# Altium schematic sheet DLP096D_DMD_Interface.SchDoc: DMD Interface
size 431 x 279 mm; Date: Not shown in title block; ApprovedBy: Not shown in title block; CheckedBy: Not shown in title block; Author: Not shown in title block; CompanyName: Not shown in title block; Engineer: Not shown in title block; Organization: Not shown in title block; Address1: Not shown in title block; Address2: Not shown in title block; Address3: Not shown in title block; Address4: Not shown in title block; DocumentNumber: 6; Revision: Use project parameter SCH_Rev; SheetNumber: 6; SheetTotal: 10; PageSetup: Record=PageOptions¦CenterHorizontal=True¦CenterVertical=True¦PrintScale=1.00¦XCorrection=1.00¦YCorrection=1.00¦PrintKind=0¦BorderSize=5000000¦LeftOffset=0¦BottomOffset=0¦Orientation=2¦PaperLength=1000¦PaperWidth=1000¦Scale=100¦PaperSource=15¦PrintQuality=600¦MediaType=1¦DitherType=10¦PaperKind=Letter¦PrintScaleMode=1
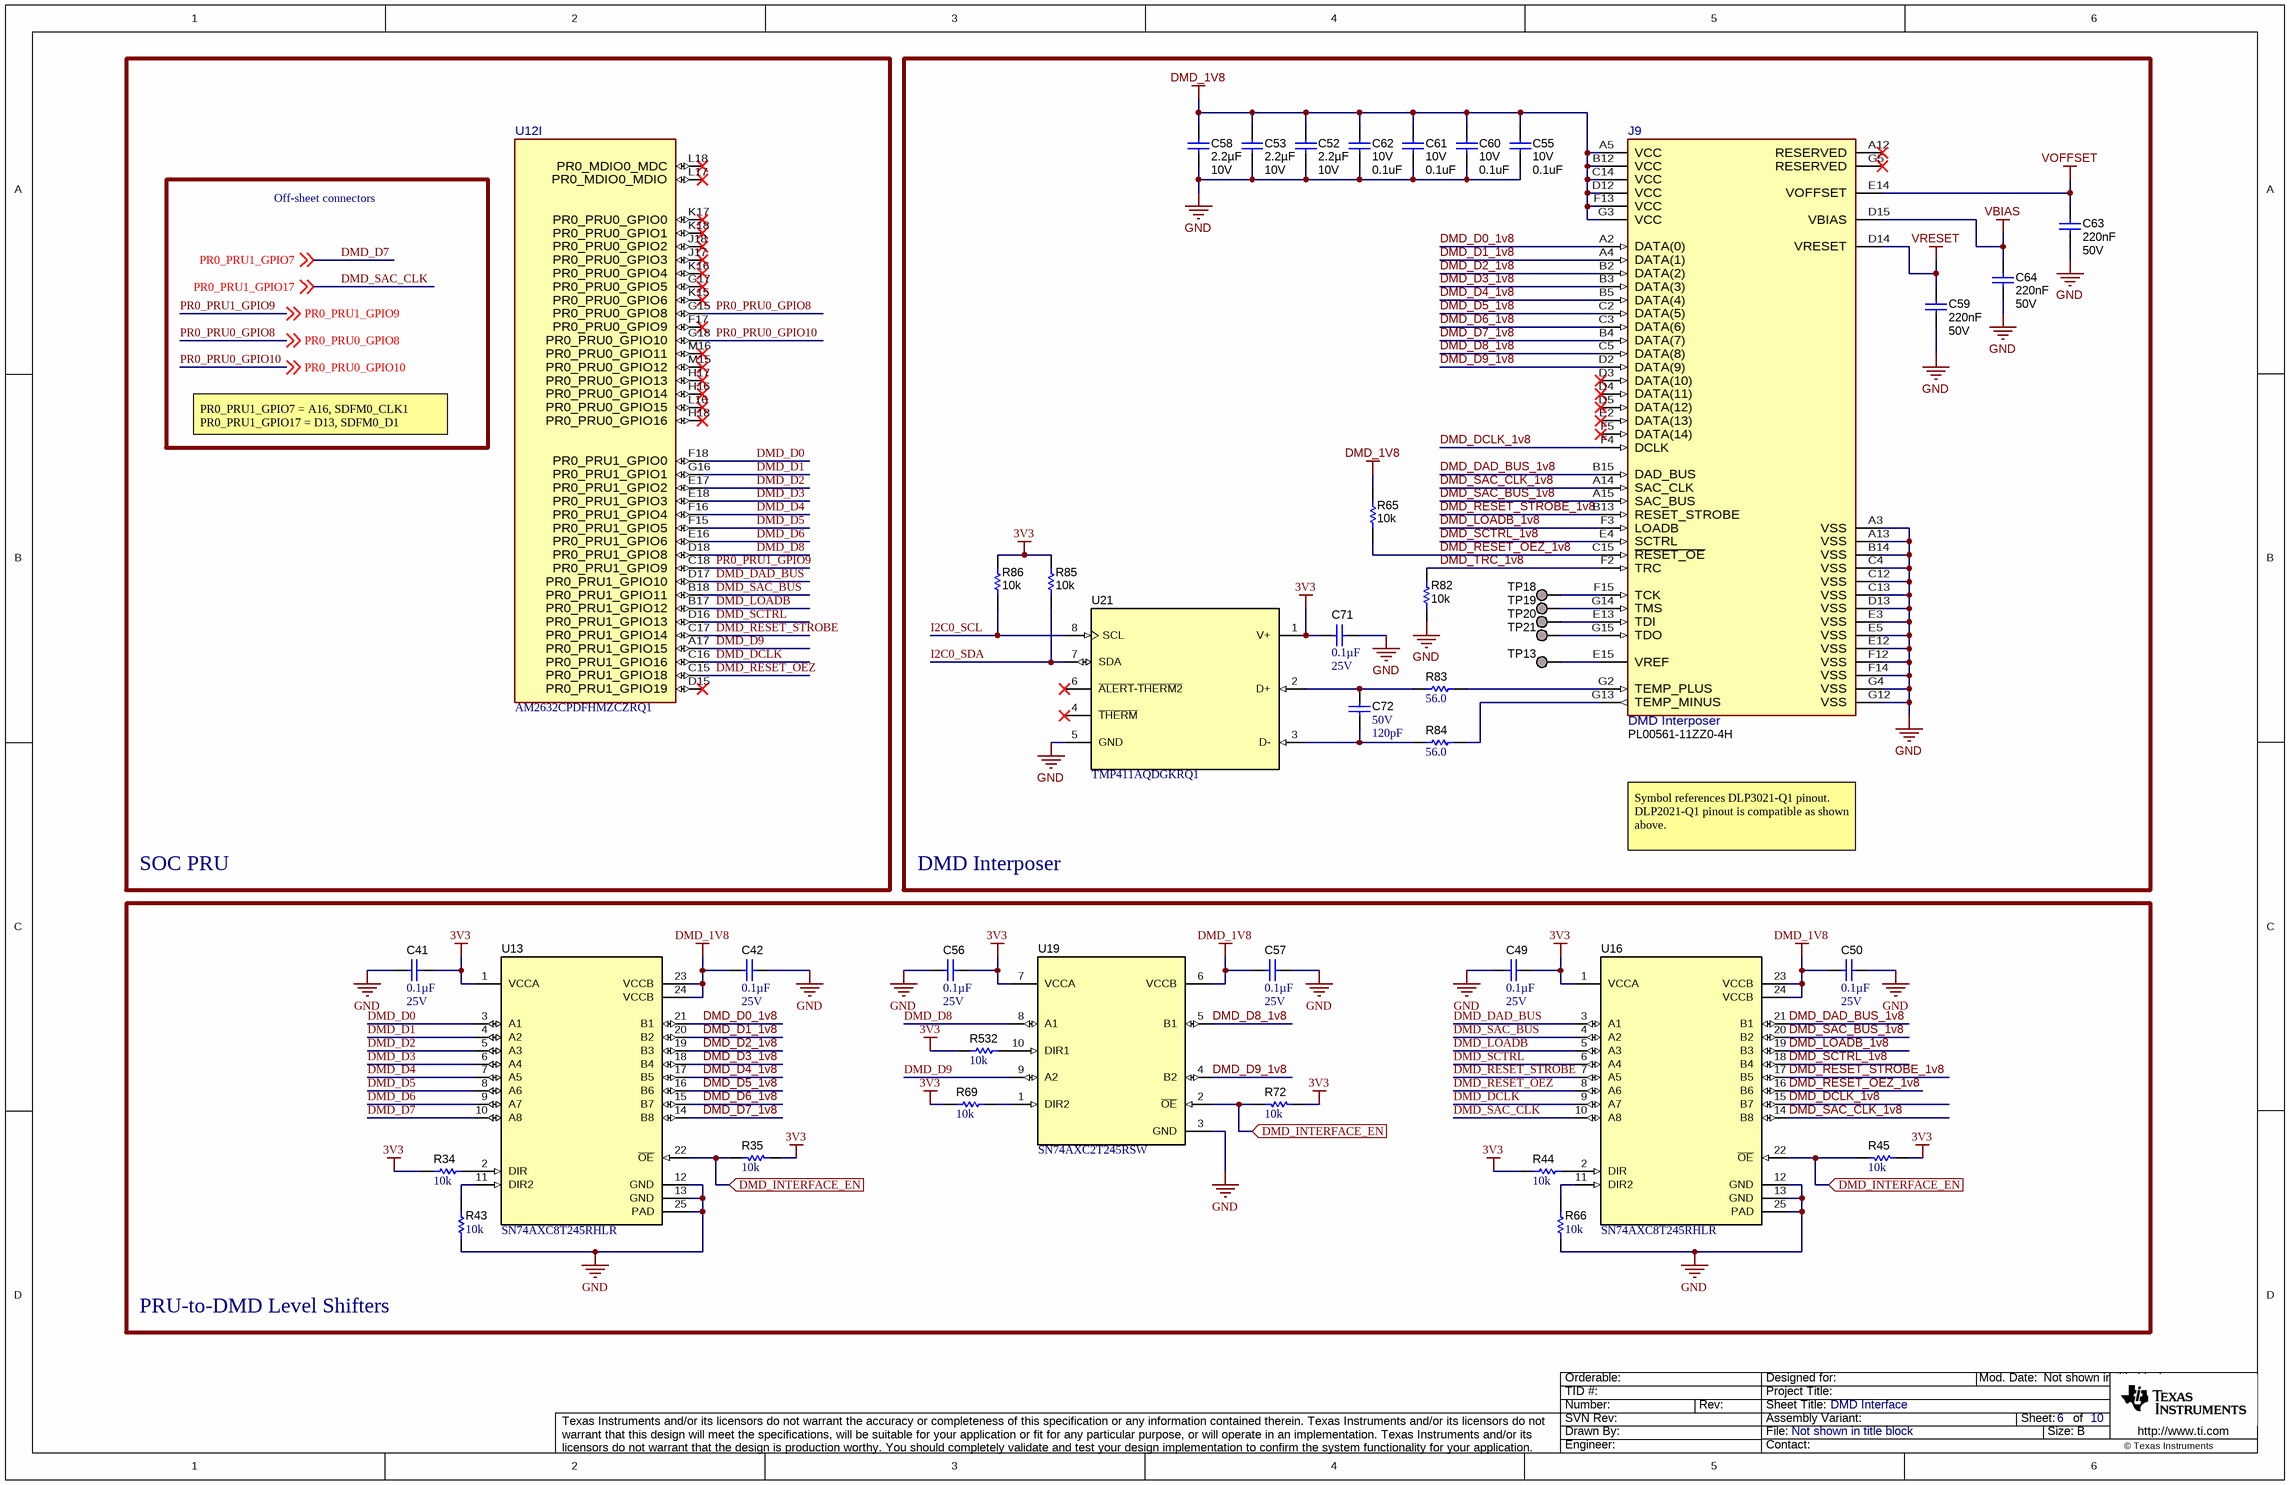
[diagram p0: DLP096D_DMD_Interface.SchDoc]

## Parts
C41  ValueDisplayed: 0.1µF  VDC_V: 25V  [0402]  (hidden comment: GCM155L81E104KE02D)
C42  ValueDisplayed: 0.1µF  VDC_V: 25V  [0402]  (hidden comment: GCM155L81E104KE02D)
C49  ValueDisplayed: 0.1µF  VDC_V: 25V  [0402]  (hidden comment: GCM155L81E104KE02D)
C50  ValueDisplayed: 0.1µF  VDC_V: 25V  [0402]  (hidden comment: GCM155L81E104KE02D)
C52  Cap_F: 2.2µF  VDC_V: 10V  [0603L]  (hidden comment: GRM188R71A225KE15J)
C53  Cap_F: 2.2µF  VDC_V: 10V  [0603L]  (hidden comment: GRM188R71A225KE15J)
C55  VDC_V: 10V  ValueDisplayed: 0.1uF  [0402L]  (hidden comment: GCM155R71A104KA55D)
C56  ValueDisplayed: 0.1µF  VDC_V: 25V  [0402]  (hidden comment: GCM155L81E104KE02D)
C57  ValueDisplayed: 0.1µF  VDC_V: 25V  [0402]  (hidden comment: GCM155L81E104KE02D)
C58  Cap_F: 2.2µF  VDC_V: 10V  [0603L]  (hidden comment: GRM188R71A225KE15J)
C59  Cap_F: 220nF  VDC_V: 50V  [0603L]  (hidden comment: GCM188R71E104KA57D)
C60  VDC_V: 10V  ValueDisplayed: 0.1uF  [0402L]  (hidden comment: GCM155R71A104KA55D)
C61  VDC_V: 10V  ValueDisplayed: 0.1uF  [0402L]  (hidden comment: GCM155R71A104KA55D)
C62  VDC_V: 10V  ValueDisplayed: 0.1uF  [0402L]  (hidden comment: GCM155R71A104KA55D)
C63  Cap_F: 220nF  VDC_V: 50V  [0603L]  (hidden comment: GCM188R71E104KA57D)
C64  Cap_F: 220nF  VDC_V: 50V  [0603L]  (hidden comment: GCM188R71E104KA57D)
C71  ValueDisplayed: 0.1µF  VDC_V: 25V  [0402]  (hidden comment: GCM155L81E104KE02D)
C72  VDC_V: 50V  ValueDisplayed: 120pF  [0402]  (hidden comment: GRM1555C1H121FA01D)
J9  DMD Interposer  PartNumber: PL00561-11ZZ0-4H  [FP-2516672_SMD_CONN_LGA-56-MFG]
R34  ValueDisplayed: 10k  [0603]  (hidden comment: CRCW060310K0JNEA)
R35  ValueDisplayed: 10k  [0603]  (hidden comment: CRCW060310K0JNEA)
R43  ValueDisplayed: 10k  [0603]  (hidden comment: CRCW060310K0JNEA)
R44  ValueDisplayed: 10k  [0603]  (hidden comment: CRCW060310K0JNEA)
R45  ValueDisplayed: 10k  [0603]  (hidden comment: CRCW060310K0JNEA)
R65  ValueDisplayed: 10k  [0201]  (hidden comment: RC0201JR-0710KL)
R66  ValueDisplayed: 10k  [0603]  (hidden comment: CRCW060310K0JNEA)
R69  ValueDisplayed: 10k  [0603]  (hidden comment: CRCW060310K0JNEA)
R72  ValueDisplayed: 10k  [0603]  (hidden comment: CRCW060310K0JNEA)
R82  ValueDisplayed: 10k  [0201]  (hidden comment: RC0201JR-0710KL)
R83  ValueDisplayed: 56.0  [0603]  (hidden comment: RC0603FR-0756RL)
R84  ValueDisplayed: 56.0  [0603]  (hidden comment: RC0603FR-0756RL)
R85  ValueDisplayed: 10k  [0201]  (hidden comment: RC0201JR-0710KL)
R86  ValueDisplayed: 10k  [0201]  (hidden comment: RC0201JR-0710KL)
R532  ValueDisplayed: 10k  [0603]  (hidden comment: CRCW060310K0JNEA)
TP13  TP_H0.45P0.75  [TP_H045P075]  (value not drawn)  (no BOM)
TP18  TP_H0.45P0.75  [TP_H045P075]  (value not drawn)  (no BOM)
TP19  TP_H0.45P0.75  [TP_H045P075]  (value not drawn)  (no BOM)
TP20  TP_H0.45P0.75  [TP_H045P075]  (value not drawn)  (no BOM)
TP21  TP_H0.45P0.75  [TP_H045P075]  (value not drawn)  (no BOM)
U12  AM2632CPDFHMZCZRQ1  [ZCZ0324A-MFG]  (part I of 13)
U13  SN74AXC8T245RHLR  [RHL0024A]
U16  SN74AXC8T245RHLR  [RHL0024A]
U19  SN74AXC2T245RSW  [RSW0010A]
U21  TMP411AQDGKRQ1  [DGK0008A_N]

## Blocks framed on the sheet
SOC PRU: U12
DMD Interposer: C52 C53 C55 C58-C64 C71 C72 J9 R65 R82-R86 TP13 TP18-TP21 U21
PRU-to-DMD Level Shifters: C41 C42 C49 C50 C56 C57 R34 R35 R43-R45 R66 R69 R72 R532 U13 U16 U19

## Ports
DMD_INTERFACE_EN (in)

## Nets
3V3: C41.1 C49.1 C56.1 C71.1 R34.1 R35.1 R44.1 R45.1 R69.2 R72.1 R85.2 R86.2 R532.1 U13.1(VCCA) U16.1(VCCA) U19.7(VCCA) U21.1(V+)
DMD_1V8: C42.2 C50.2 C52.1 C53.1 C55.1 C57.2 C58.1 C60.1 C61.1 C62.1 J9.A5(VCC) J9.B12(VCC) J9.C14(VCC) J9.D12(VCC) J9.F13(VCC) J9.G3(VCC) R65.2 U13.23(VCCB) U13.24(VCCB) U16.23(VCCB) U16.24(VCCB) U19.6(VCCB)
GND: C41.2 C42.1 C49.2 C50.1 C52.2 C53.2 C55.2 C56.2 C57.1 C58.2 C59.2 C60.2 C61.2 C62.2 C63.2 C64.2 C71.2 J9.A3(VSS) J9.A13(VSS) J9.B14(VSS) J9.C4(VSS) J9.C12(VSS) J9.C13(VSS) J9.D13(VSS) J9.E3(VSS) J9.E5(VSS) J9.E12(VSS) J9.F12(VSS) J9.F14(VSS) J9.G4(VSS) J9.G12(VSS) R43.1 R66.1 R82.1 U13.12(GND) U13.13(GND) U13.25(PAD) U16.12(GND) U16.13(GND) U16.25(PAD) U19.3(GND) U21.5(GND)
VBIAS: C64.1 J9.D15(VBIAS)
VOFFSET: C63.1 J9.E14(VOFFSET)
VRESET: C59.1 J9.D14(VRESET)
DMD_D0: U12.F18(PR0_PRU1_GPIO0) U13.3(A1)
DMD_D0_1v8: J9.A2(DATA(0)) U13.21(B1)
DMD_D1: U12.G16(PR0_PRU1_GPIO1) U13.4(A2)
DMD_D1_1v8: J9.A4(DATA(1)) U13.20(B2)
DMD_D2: U12.E17(PR0_PRU1_GPIO2) U13.5(A3)
DMD_D2_1v8: J9.B2(DATA(2)) U13.19(B3)
DMD_D3: U12.E18(PR0_PRU1_GPIO3) U13.6(A4)
DMD_D3_1v8: J9.B3(DATA(3)) U13.18(B4)
DMD_D4: U12.F16(PR0_PRU1_GPIO4) U13.7(A5)
DMD_D4_1v8: J9.B5(DATA(4)) U13.17(B5)
DMD_D5: U12.F15(PR0_PRU1_GPIO5) U13.8(A6)
DMD_D5_1v8: J9.C2(DATA(5)) U13.16(B6)
DMD_D6: U12.E16(PR0_PRU1_GPIO6) U13.9(A7)
DMD_D6_1v8: J9.C3(DATA(6)) U13.15(B7)
DMD_D7: U13.10(A8) ; off-sheet PR0_PRU1_GPIO7  [also labelled PR0_PRU1_GPIO7]
DMD_D7_1v8: J9.B4(DATA(7)) U13.14(B8)
DMD_D8: U12.D18(PR0_PRU1_GPIO8) U19.8(A1)
DMD_D8_1v8: J9.C5(DATA(8)) U19.5(B1)
DMD_D9: U12.A17(PR0_PRU1_GPIO15) U19.9(A2)
DMD_D9_1v8: J9.D2(DATA(9)) U19.4(B2)
DMD_DAD_BUS: U12.D17(PR0_PRU1_GPIO10) U16.3(A1)
DMD_DAD_BUS_1v8: J9.B15(DAD_BUS) U16.21(B1)
DMD_DCLK: U12.C16(PR0_PRU1_GPIO16) U16.9(A7)
DMD_DCLK_1v8: J9.F4(DCLK) U16.15(B7)
DMD_INTERFACE_EN: R35.2 R45.2 R72.2 U13.22(~{OE}) U16.22(~{OE}) U19.2(~{OE}) ; port DMD_INTERFACE_EN
DMD_LOADB: U12.B17(PR0_PRU1_GPIO12) U16.5(A3)
DMD_LOADB_1v8: J9.F3(LOADB) U16.19(B3)
DMD_RESET_OEZ: U12.C15(PR0_PRU1_GPIO18) U16.8(A6)
DMD_RESET_OEZ_1v8: J9.C15(~{RESET_OE}) R65.1 U16.16(B6)
DMD_RESET_STROBE: U12.C17(PR0_PRU1_GPIO14) U16.7(A5)
DMD_RESET_STROBE_1v8: J9.B13(RESET_STROBE) U16.17(B5)
DMD_SAC_BUS: U12.B18(PR0_PRU1_GPIO11) U16.4(A2)
DMD_SAC_BUS_1v8: J9.A15(SAC_BUS) U16.20(B2)
DMD_SAC_CLK: U16.10(A8) ; off-sheet PR0_PRU1_GPIO17  [also labelled PR0_PRU1_GPIO17]
DMD_SAC_CLK_1v8: J9.A14(SAC_CLK) U16.14(B8)
DMD_SCTRL: U12.D16(PR0_PRU1_GPIO13) U16.6(A4)
DMD_SCTRL_1v8: J9.E4(SCTRL) U16.18(B4)
DMD_TRC_1v8: J9.F2(TRC) R82.2
I2C0_SCL: R86.1 U21.8(SCL)
I2C0_SDA: R85.1 U21.7(SDA)
PR0_PRU0_GPIO8: U12.G15(PR0_PRU0_GPIO8) ; off-sheet PR0_PRU0_GPIO8
PR0_PRU0_GPIO10: U12.G18(PR0_PRU0_GPIO10) ; off-sheet PR0_PRU0_GPIO10
PR0_PRU1_GPIO9: U12.C18(PR0_PRU1_GPIO9) ; off-sheet PR0_PRU1_GPIO9
NetC72_1: C72.1 R83.1 U21.2(D+)
NetC72_2: C72.2 R84.1 U21.3(D-)
NetJ9_E13: J9.E13(TDI) TP20.1
NetJ9_E15: J9.E15(VREF) TP13.1
NetJ9_F15: J9.F15(TCK) TP18.1
NetJ9_G2: J9.G2(TEMP_PLUS) R83.2
NetJ9_G13: J9.G13(TEMP_MINUS) R84.2
NetJ9_G14: J9.G14(TMS) TP19.1
NetJ9_G15: J9.G15(TDO) TP21.1
NetR34_2: R34.2 U13.2(DIR)
NetR43_2: R43.2 U13.11(DIR2)
NetR44_2: R44.2 U16.2(DIR)
NetR66_2: R66.2 U16.11(DIR2)
NetR69_1: R69.1 U19.1(DIR2)
NetR532_2: R532.2 U19.10(DIR1)

Not connected (* = marked no-connect by the designer): J9 A12(RESERVED)* D3(DATA(10))* D4(DATA(11))* D5(DATA(12))* E2(DATA(13))* F5(DATA(14))* G5(RESERVED)*; U12 D15(PR0_PRU1_GPIO19)* F17(PR0_PRU0_GPIO9)* G17(PR0_PRU0_GPIO5)* H16(PR0_PRU0_GPIO14)* H17(PR0_PRU0_GPIO13)* H18(PR0_PRU0_GPIO16)* J17(PR0_PRU0_GPIO3)* J18(PR0_PRU0_GPIO2)* K15(PR0_PRU0_GPIO6)* K16(PR0_PRU0_GPIO4)* K17(PR0_PRU0_GPIO0)* K18(PR0_PRU0_GPIO1)* L16(PR0_PRU0_GPIO15)* L17(PR0_MDIO0_MDIO)* L18(PR0_MDIO0_MDC)* M15(PR0_PRU0_GPIO12)* M16(PR0_PRU0_GPIO11)*; U21 4(~{THERM})* 6(~{ALERT}-~{THERM2})*

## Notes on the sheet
- Off-sheet connectors
- PR0_PRU1_GPIO7 = A16, SDFM0_CLK1
  PR0_PRU1_GPIO17 = D13, SDFM0_D1
- Symbol references DLP3021-Q1 pinout. DLP2021-Q1 pinout is compatible as shown above.

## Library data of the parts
C41 C42 C49 C50 C56 C57 C71 = CMP-0861000-1: CAP, CERM, 0.1 µF, 25 V,+/- 10%, X8L, AEC-Q200 Grade 0, 0402; Manufacturer: MuRata; U/M: EA; Polarized: N; Cap_F: 100nF; SizeZ_mm: 0.6; SizeY_mm: 0.5; Value: 0.1uF; SizeX_mm: 1; AEC Qualified: Y; AEC Grade: 0; SizeAreaWB_mm2: 3; AEC Category: Q200; TaMin_C: -55°C; TaMax_C: 150°C
C52 C53 C58 = CMP-0084284-1: CAP, CERM, 2.2 µF, 10 V,+/- 10%, X7R, AEC-Q200 Grade 1, 0603; Manufacturer: MuRata; SizeAreaWB_mm2: 4.68; Polarized: N; AEC Qualified: Y; SizeX_mm: 1.6; SizeZ_mm: 1; SizeY_mm: 0.8; U/M: EA; TaMin_C: -55°C; Value: 2.2uF; Cap_Case: 0603; AEC Category: Q200; TaMax_C: 125°C; SizeArea_mm2: 1.28
C55 C60-C62 = CMP-0006350-2: CAP, CERM, 0.1 uF, 10 V, +/- 10%, X7R, AEC-Q200 Grade 1, 0402; Manufacturer: MuRata; TaMin_C: -55°C; Polarized: N; SizeAreaWB_mm2: 3; Value1: Unknown; U/M: EA; Value: 0.1uF; TaMax_C: 125°C; SizeZ_mm: 0.6; SizeX_mm: 1; SizeY_mm: 0.5; Cap_Case: 0402; AEC Qualified: Y; Cap_F: 100nF; AEC Category: Q200
C59 C63 C64 = CMP-0007094-5: CAP, CERM, 0.22 uF, 50 V, +/- 10%, X7R, AEC-Q200 Grade 1, 0603; Manufacturer: TDK; PartNumber: CGA3E3X7R1H224K080AB; TaMin_C: -55°C; ESR_ohm: 0.021699; Polarized: N; SizeAreaWB_mm2: 4.68; Value1: 0.021699 ohm; U/M: EA; Value: 0.22uF; TaMax_C: 125°C; SizeZ_mm: 1; SizeX_mm: 1.6; SizeY_mm: 0.8; Cap_Case: 0603; SizeArea_mm2: 1.28; AEC Qualified: Y; IRMS_A: 1.12496A; AEC Category: Q200
C72 = CMP-0006416-2: CAP, CERM, 120 pF, 50 V, +/- 1%, C0G/NP0, 0402; Manufacturer: MuRata; TaMin_C: -55°C; Polarized: N; SizeAreaWB_mm2: 3; Value1: Unknown; U/M: EA; Value: 120pF; TaMax_C: 125°C; SizeZ_mm: 0.6; SizeX_mm: 1; SizeY_mm: 0.5; AEC Category: Q200
J9 = CMP-0087816-2: NTERPOSER, 56 CONTACT, HOLE DATUM; Alternate Manufacturer: Neoconix; Alternate PartNumber: BDX0056DMMSXAU00; Manufacturer: Foxconn Interconnect Technology; DUT-Pitch_mm: 1mm; SizeZ_mm: 1.4mm
R34 R35 R43-R45 R66 R69 R72 R532 = CMP-0025701-1: RES, 10 k, 5%, 0.1 W, 0603; Manufacturer: Vishay-Dale; Power_W: 100mW; TempCo: 200 ppm/C; Value_Code: 10k0; U/M: EA; Value: 10k; EIA_Code: E24; SizeX_mm: 1.6; SizeY_mm: 0.8; SizeZ_mm: 1; Value2: 0.1W; SizeArea_mm2: 1.28; VDC_V: 75V; AEC Category: Q200
R65 R82 R85 R86 = CMP-0027019-1: RES, 10 k, 5%, 0.05 W, 0201; Manufacturer: Yageo America; Power_W: 50mW; TempCo: 200 ppm/C; Value_Code: 10k0; U/M: EA; Value: 10k; EIA_Code: E24; SizeX_mm: 0.6; SizeY_mm: 0.3; SizeZ_mm: 0.26; Value2: 0.05W; SizeArea_mm2: 0.18; AEC Qualified: N; VDC_V: 25V; AEC Category: Q200
R83 R84 = CMP-0023188-5: RES, 56.0, 1%, 0.1 W, 0603; Manufacturer: Yageo; Power_W: 100mW; TempCo: 100 ppm/C; Value_Code: 56R0; Value: 56.0; Res_ohm: 56; SizeX_mm: 1.6; SizeY_mm: 0.8; SizeZ_mm: 1; Value2: 0.1W; SizeArea_mm2: 1.28; AEC Qualified: N; VDC_V: 75V; AEC Category: Q200; SizeAreaWB_mm2: 4.68
TP13 TP18-TP21 = CMP-0003719-1: Testpoint; Manufacturer: Texas Instruments; CompType: Pad
U12 = CMP-0093674-1: Sitara™ Microcontrollers; Manufacturer: Texas Instruments; Min Supply Voltage: 1.14V; Number Of Adc Channels: 30; AEC Qualified: No; TJmax_C: +105°C; Memory Type: SRAM; Standoff Height: 0.35mm; Core Architecture: ARM Cortex-R5F; Number Of I2C Channels: 4; Number Of Pwm Channels: 24; Number Of Spi Channels: 5; Number Of Cores: 2; Frequency_Fixed: 400MHz; Nominal Supply Current: 200-2500mA; Ram Size: 2MBytes; Number Of Ethernet Channels: 1; Interface: I2C,SPI,UART,CAN,LIN,Ethernet,Other; Data Bus Width: 64bits; SizeZ_mm: 1.4mm; Number Of Uart Channels: 6; Number Of I/Os: 140; Max Supply Voltage: 3.465V
U13 U16 = CMP-0065229-3: Asynchronous Communication Between Data Buses, RHL0024A (VQFN-24); Manufacturer: Texas Instruments; Alternate PartNumber: SN74AXC8T245RHLT; SizeX_mm: 3.5; SizeY_mm: 5.5; CompType: IC; SizeZ_mm: 1.0; SizeArea_mm2: 19.25; SizeAreaWB_mm2: 41.25; AEC Category: Q200; AEC Qualified: N
U19 = CMP-0860382-1: SN74AXC2T245RSW, RSW0010A (UQFN-10); Alternate Manufacturer: Texas Instruments; SizeZ_mm: 0.55; AEC Qualified: N; SizeArea_mm2: 2.52; CompType: IC; SizeX_mm: 1.4; SizeY_mm: 1.8; AEC Category: Q200; SizeAreaWB_mm2: 6.72
U21 = CMP-0860146-1: Automotive Grade, Remote and Local Temperature Sensor with N-Factor and Series-R Correction, DGK0008A (VSSOP-8); Alternate Manufacturer: Texas Instruments; SizeAreaWB_mm2: 23.6; SizeArea_mm2: 14.7; SizeX_mm: 4.9; AEC Category: Q200; SizeZ_mm: 1.1; CompType: IC; AEC Qualified: Y; SizeY_mm: 3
